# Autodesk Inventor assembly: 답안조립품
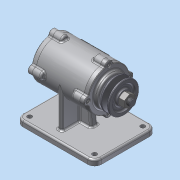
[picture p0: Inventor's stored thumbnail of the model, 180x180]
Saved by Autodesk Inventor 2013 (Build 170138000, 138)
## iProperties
Created: 2015-12
Part Number: 답안조립품
Document SubType Name: Assembly
Designer: dgall
Author: dgall
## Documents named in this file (11)
- C:\Users\dgall\Desktop\451207V1025\답안조립품.iam
- C:\Users\dgall\Desktop\451207V1025\본체.ipt
- C:\Users\dgall\Desktop\451207V1025\베어링 6204.ipt
- C:\Users\dgall\Desktop\451207V1025\커버.ipt
- C:\Users\dgall\Desktop\451207V1025\커버2.ipt
- C:\Users\dgall\Desktop\451207V1025\오일실.ipt
- C:\Users\dgall\Desktop\451207V1025\V-벨트풀리.ipt
- C:\Users\dgall\Desktop\451207V1025\축.ipt
- C:\Users\dgall\Desktop\451207V1025\키(4 x 4 x 12).ipt
- C:\Users\dgall\Desktop\451207V1025\너트 M12x1.25.ipt
- C:\Users\dgall\Desktop\451207V1025\볼트 M4 x 12.ipt
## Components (6 placed, 5 different names)
1. KS B 2023 6204 - 20 x 47 x 14:1
2. KS B 2023 6204 - 20 x 47 x 14:2
3. KS B 2804 D D - 20 32 8:1
4. V-벨트풀리:1
5. KS B 1311 (I) 4 x 4 x 12:1 — 각도:1
6. KS B 1012 클래스 1 일반 - 미터 M12x1.25:1
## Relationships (1: Angle 1)
- 각도:1 [Angle]: KS B 1311 (I) 4 x 4 x 12:1
